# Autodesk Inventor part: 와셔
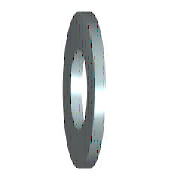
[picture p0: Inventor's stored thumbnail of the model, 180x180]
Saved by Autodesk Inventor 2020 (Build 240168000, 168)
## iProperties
IsCustomPart: 1
Created: 2012-02
Part Number: 와셔
Material: 강철, 연강
Description: 평면 와셔
Document SubType Name: Modeling
Standard: KS B 1326
Designer: mduedu
Standards Organization: KS
Language: ko-KR
Size Designation: 8x15.5
Categories: <MemberInstance><Categories><Category DisplayName="조임쇠" InternalName="e4da775c-781d-43d5-af7c-5136215cf5a6" Mnemonic="FSTN"><Category DisplayName="와셔" InternalN
Density: 1 g/cm^3
Appearance: 주황색
Author: mduedu
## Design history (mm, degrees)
sketch "스케치"
  geometry: C1 r 7.75 at (0, 0); C2 r 4.2 at (0, 0); 1 further point
  constraints: 2 centre point, 2 coincident
  dimensions: "d0" = 8.4 diameter of C2 (= SD1); "d1" = 15.5 diameter of C1 (= SD2)
extrude "본체" new body sketch "스케치" distance "d2" = 1.6 (= SD); taper "d3" = 0 deg
workaxis "Work Axis1"
workplane "Work Plane1"
body "Solid1"
other parameters: "SD1" = 8.4 [user parameter; used in 1 equation term], "SD2" = 15.5 [user parameter; used in 1 equation term], "SD" = 1.6 [user parameter; used in 1 equation term], "d4" = 0, "d5" = 0, "d6" = 0, "d7" = 0, "NND" = 8 [user parameter]
